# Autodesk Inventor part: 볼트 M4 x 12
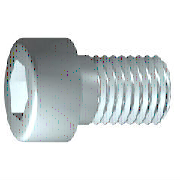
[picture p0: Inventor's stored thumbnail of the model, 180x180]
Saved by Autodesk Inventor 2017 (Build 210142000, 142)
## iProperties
IsCustomPart: 0
Created: 2012-02
Part Number: 볼트 M4 x 12
Material: 강철, 연강
Description: 6각 소켓 머리 캡 나사
Document SubType Name: Modeling
Standard: ISO 4762
Designer: mduedu
Standard Revision: Fourth edition 2004-03-01
Standards Organization: ISO
Language: ko-KR
Size Designation: M4 x 12
Categories: <MemberInstance><Categories><Category DisplayName="조임쇠" InternalName="e4da775c-781d-43d5-af7c-5136215cf5a6" Mnemonic="FSTN"><Category DisplayName="볼트" InternalN
Density: 7.86 g/cm^3
Mass: 2.23465 g
Surface Area: 3.30853 cm^2
Volume: 0.284306 cm^3
Appearance: 강철
Author: mduedu
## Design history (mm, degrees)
sketch "스케치1"
  geometry: L1 (-1, 0)-(12, 0); L2 (12, 0)-(12, 2); L3 (12, 2)-(1.75, 2); L4 (1.75, 2)-(1.32, 2); L5 (1.32, 2)-(0, 2); L6 (0, 2)-(0, 3.5); L7 (0, 3.5)-(-4, 3.5); L8 (-4, 3.5)-(-4, 1.732); L9 (-4, 1.732)-(-2, 1.732); L10 (-2, 1.732)-(-1, 0); L11 (-7.2, 0)-(15.2, 0) reference; L12 (0, -0.7)-(0, 4.2) reference; L13 (1.75, 2)-(0, 2)
  constraints: 22 end point, 6 parallel, 2 collinear, 2 perpendicular, 1 horizontal, 1 point on line
  dimensions: "d1" = 10.25 distance from line of L3.end L2 (= GEL); "d2" = 0.42952 distance of L4.end L3.end (computed from GAL); "d3" = 4 distance between parallel lines of L8 L6 (= KOH); "d4" = 2 distance of L8.end L9.end (= INTI); "d5" = 60 deg angle of L10 L1; "d6" = 4 diameter of L3 L1 (= GD); "d7" = 4 diameter of L5 L1 (= BDM); "d8" = 3.4641 diameter of L9 L1 (= 1.1547 x SW); "d9" = 7 diameter of L7 L1 (= KOD); "d26" = 12 distance between parallel lines of L12 L2 (= NLG)
revolve "본체" sketch "스케치1" stored, may be unused: angle "d10" = 90 deg
sketch "스케치2"
  geometry: L1 (0, -4.9)-(0, 4.9) reference; L2 (-4.9, 0)-(4.9, 0) reference; L3 (1.732, 0)-(0.866, -1.5); L4 (0.866, -1.5)-(-0.866, -1.5); L5 (-0.866, -1.5)-(-1.732, 0); L6 (-1.732, 0)-(-0.866, 1.5); L7 (-0.866, 1.5)-(0.866, 1.5); L8 (0.866, 1.5)-(1.732, 0); 2 further points
  constraints: 12 end point, 1 coincident, 1 horizontal alignment, 1 point on line, 12 other
extrude "슬롯" join sketch "스케치2" stored distance "d11" = 10; taper "d12" = 0 deg
workplane "Work Plane1"
fillet "Fillet2" dims "d30" = 0.1 (= R)
body "Solid1"
fillet "모깎기1" dims "d17" = 0.4 (= RR)
feature "스레드" dims "d13" = 10.25 (= GEL), "d14" = 0
chamfer "모따기1" distance "d15" = 0.42941 (= -0.5 x SPD + 0.5 x GD); stored, may be unused: second distance "d16" = 0.42941 (= GUL), angle "d27" = 45 deg
other parameters: "GD" = 4 [user parameter; used in 2 equation terms], "NLG" = 12 [user parameter; used in 1 equation term], "GEL" = 10.25 [user parameter; used in 2 equation terms], "KOD" = 7 [user parameter; used in 1 equation term], "KOH" = 4 [user parameter; used in 1 equation term], "INTI" = 2 [user parameter; used in 1 equation term], "GAL" = 0.42941 (= 0.61345 x PTC) [user parameter; used in 1 equation term], "GUL" = 0.42941 (= 0.61345 x PTC) [user parameter; used in 1 equation term], "BDM" = 4 (= NND) [user parameter; used in 1 equation term], "SW" = 3 [user parameter; used in 2 equation terms], "RR" = 0.4 [user parameter; used in 1 equation term], "SPD" = 3.14117 (= NND - 1.2269 x PTC) [user parameter; used in 1 equation term], "d19" = 0, "d28" = 0, "d29" = 0, "R" = 0.1 [user parameter; used in 1 equation term], "TOA" = 30 deg [user parameter], "GD1" = 3.14117 (= THREADDIA - 1.2269 x PTC) [user parameter], "THREADDIA" = 4 [user parameter; used in 1 equation term], "FAWI" = 45 deg [user parameter], "TPU" = 14.28571 (computed from PTC) [user parameter], "PTC" = 0.7 [user parameter; used in 5 equation terms], "NND" = 4 [user parameter; used in 2 equation terms], "E0" = 3.465 (= 1.155 x SW) [user parameter]
